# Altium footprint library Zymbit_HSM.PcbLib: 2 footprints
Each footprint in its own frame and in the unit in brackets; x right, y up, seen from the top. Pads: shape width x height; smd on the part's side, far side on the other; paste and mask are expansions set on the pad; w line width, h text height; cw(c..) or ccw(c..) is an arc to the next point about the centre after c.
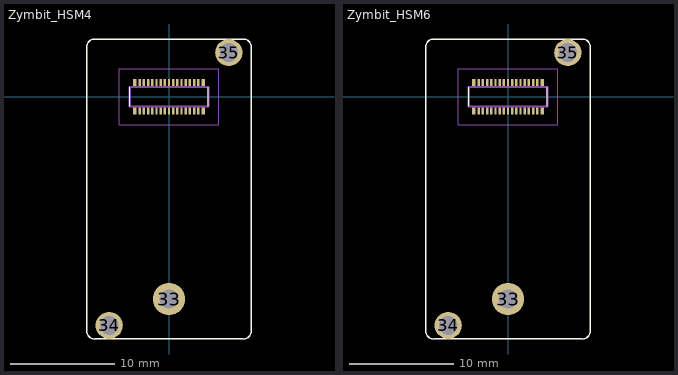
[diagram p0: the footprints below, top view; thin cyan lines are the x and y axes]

## Zymbit_HSM4 [mm]
pads (37):
  rect 0.23x0.66 smd: 1(2.8,-1.355) 2(2.8,1.355) 3(2.4,-1.355) 4(2.4,1.355) 5(2,-1.355) 6(2,1.355) 7(1.6,-1.355) 8(1.6,1.355) 9(1.2,-1.355) 10(1.2,1.355) 11(0.8,-1.355) 12(0.8,1.355) 13(0.4,-1.355) 14(0.4,1.355) 15(0,-1.355) 16(0,1.355) 17(-0.4,-1.355) 18(-0.4,1.355) 19(-0.8,-1.355) 20(-0.8,1.355) 21(-1.2,-1.355) 22(-1.2,1.355) 23(-1.6,-1.355) 24(-1.6,1.355) 25(-2,-1.355) 26(-2,1.355) 27(-2.4,-1.355) 28(-2.4,1.355) 29(-2.8,-1.355) 30(-2.8,1.355)
  round 3.1 hole 1.8: 33(0,-19.371)
  round 2.6 hole 1.8: 34(-5.73,-21.9) 35(5.73,4.24)
  rect 0.35x0.66 smd: MP1(3.275,-1.355) MP2(3.275,1.355) MP3(-3.275,-1.355) MP4(-3.275,1.355)
Top Overlay:
  lines w0.1: -3.76,-0.925 -3.76,0.925 ; 3.76,-0.925 3.76,0.925
  lines w0.127: -7.125,-23.2 7.125,-23.2 ; -7.12,-23.2 cw(c-7.12,-22.45) -7.87,-22.45 -7.87,4.79 cw(c-7.12,4.79) -7.12,5.54 7.075,5.54 ; 7.12,-23.2 ccw(c7.12,-22.45) 7.87,-22.45 ; 7.12,5.54 cw(c7.12,4.79) 7.87,4.79 ; 7.87,-22.475 7.87,4.8
Mechanical 13:
  lines w0.2: -3.76,-0.925 3.76,-0.925 3.76,0.925 -3.76,0.925 -3.76,-0.925
Mechanical 15:
  lines w0.1: -4.76,-2.685 4.76,-2.685 4.76,2.685 -4.76,2.685 -4.76,-2.685
3D body "HSM Can REV D 1.1.4 (HSM4).STEP": height 7.71, standoff 0, extent -7.875,-23.193 7.863,5.55
3D body "DF40C-30DP.stp": height 1.13, standoff -0.01, extent -3.75,-1.49 3.77,1.48

## Zymbit_HSM6 [mm]
pads (37):
  rect 0.23x0.66 smd: 1(2.8,-1.355) 2(2.8,1.355) 3(2.4,-1.355) 4(2.4,1.355) 5(2,-1.355) 6(2,1.355) 7(1.6,-1.355) 8(1.6,1.355) 9(1.2,-1.355) 10(1.2,1.355) 11(0.8,-1.355) 12(0.8,1.355) 13(0.4,-1.355) 14(0.4,1.355) 15(0,-1.355) 16(0,1.355) 17(-0.4,-1.355) 18(-0.4,1.355) 19(-0.8,-1.355) 20(-0.8,1.355) 21(-1.2,-1.355) 22(-1.2,1.355) 23(-1.6,-1.355) 24(-1.6,1.355) 25(-2,-1.355) 26(-2,1.355) 27(-2.4,-1.355) 28(-2.4,1.355) 29(-2.8,-1.355) 30(-2.8,1.355)
  round 3.1 hole 1.8: 33(0,-19.371)
  round 2.6 hole 1.8: 34(-5.73,-21.9) 35(5.73,4.24)
  rect 0.35x0.66 smd: MP1(3.275,-1.355) MP2(3.275,1.355) MP3(-3.275,-1.355) MP4(-3.275,1.355)
Top Overlay:
  lines w0.1: -3.76,-0.925 -3.76,0.925 ; 3.76,-0.925 3.76,0.925
  lines w0.127: -7.125,-23.2 7.125,-23.2 ; -7.12,-23.2 cw(c-7.12,-22.45) -7.87,-22.45 -7.87,4.79 cw(c-7.12,4.79) -7.12,5.54 7.075,5.54 ; 7.12,-23.2 ccw(c7.12,-22.45) 7.87,-22.45 ; 7.12,5.54 cw(c7.12,4.79) 7.87,4.79 ; 7.87,-22.475 7.87,4.8
Mechanical 13:
  lines w0.2: -3.76,-0.925 3.76,-0.925 3.76,0.925 -3.76,0.925 -3.76,-0.925
Mechanical 15:
  lines w0.1: -4.76,-2.685 4.76,-2.685 4.76,2.685 -4.76,2.685 -4.76,-2.685
3D body "DF40C-30DP.stp": height 1.13, standoff -0.01, extent -3.75,-1.49 3.77,1.48
3D body "HSM Can REV D 1.1.4 (HSM6).STEP": height 7.71, standoff 0, extent -7.875,-23.193 7.863,5.55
